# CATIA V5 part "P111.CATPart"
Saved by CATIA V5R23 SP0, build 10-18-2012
Part number: P111
Definition: goupille
Bounding box of the stored display mesh (mm): x -4 to 4, y -9 to 9, z -4 to 4
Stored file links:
  C:\wamp\www\COURS\CONCEPTION GMP1\TITRE 02-SEMESTRE 2\03-TP7-PRESSE MECANIQUE\eleve\P111.CATPart
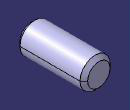
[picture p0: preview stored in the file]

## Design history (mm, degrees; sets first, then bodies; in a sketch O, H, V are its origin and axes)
Body1 (main body)
  Sketch1 on zx-plane, origin (0, 0, 0), H (-1, 0, 0), V (0, 0, 1)
    circle A1 centre (0, 0) radius 4
    radius A1 = 4
  Pad1: profile Sketch1, direction (0, 1, 0), length 9, mirrored extent
  Chamfer1: length 1, angle 45, on edge [face of Pad1 | face of Pad1] (x2)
